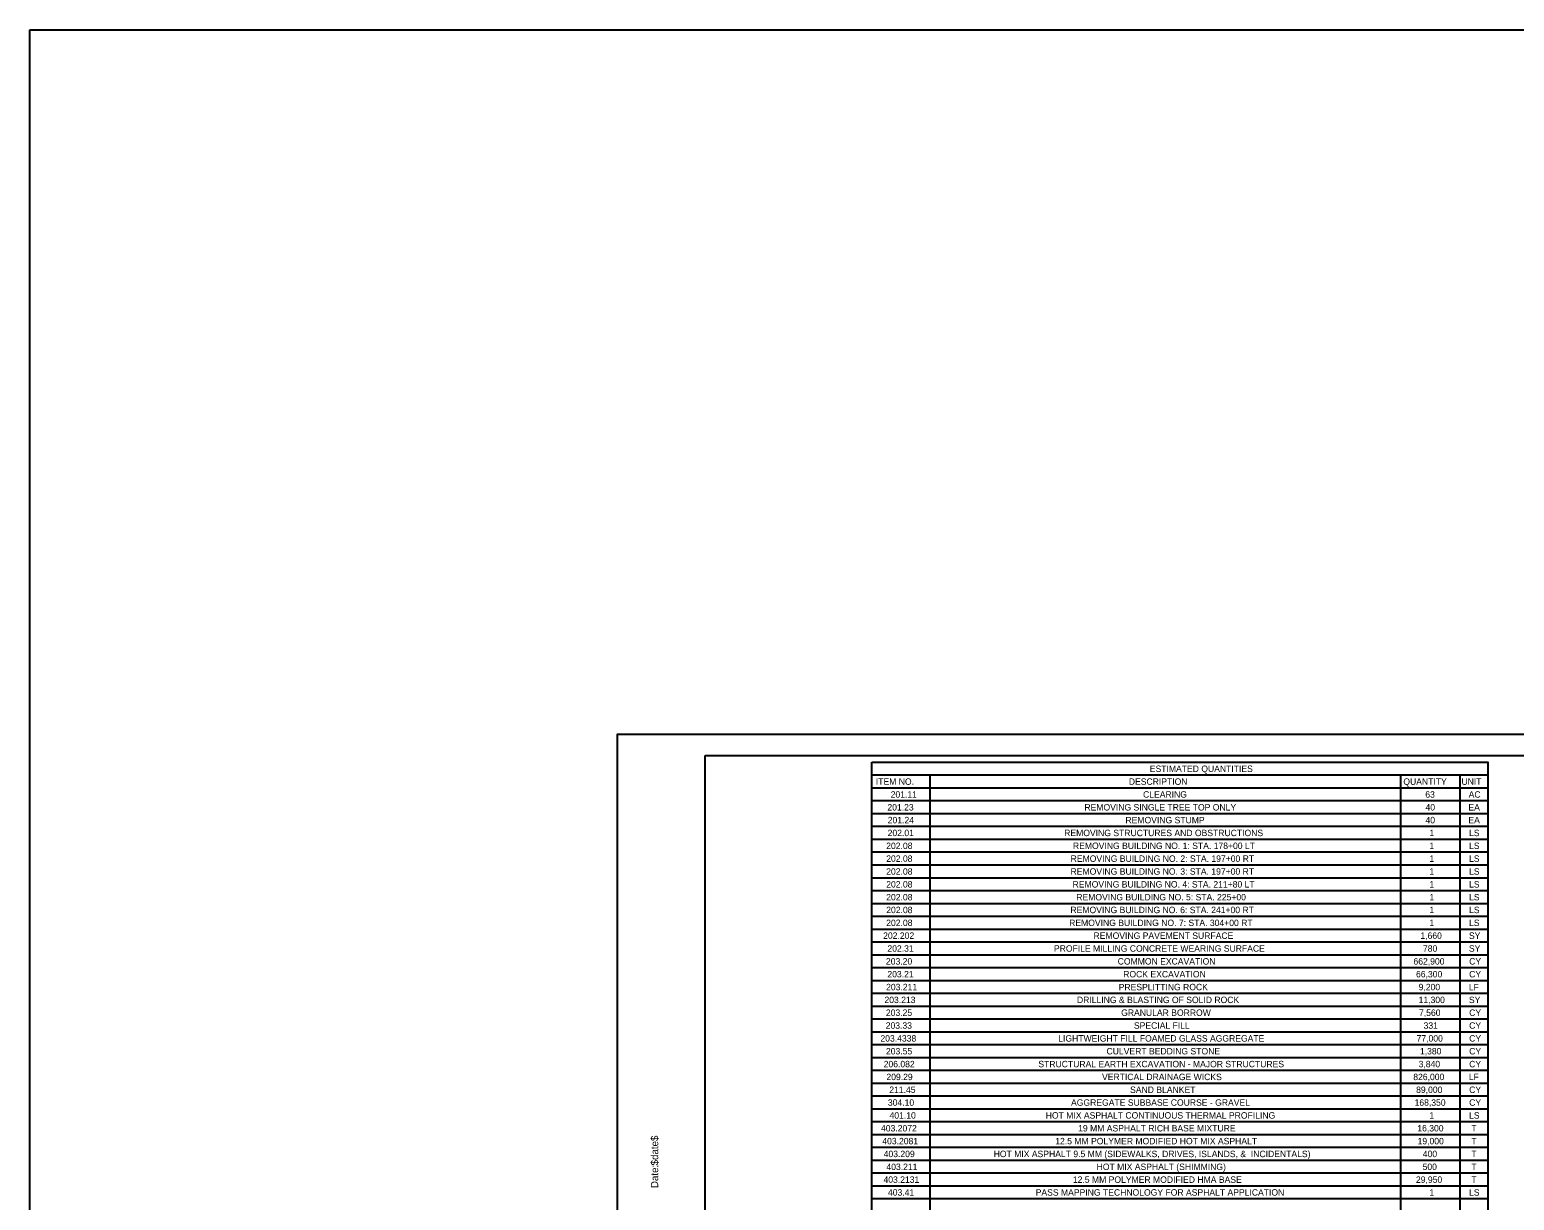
# Model space of a CAD drawing. Extents: x -18.7 to 5.6, y -2.7 to 5.1.
# Drawn here: x -10.815 to -8.539, y 3.303 to 5.098 of the extents above; entities that cross this region are included whole.
import ezdxf

# ---------------------------------------------------------------- set-up
doc = ezdxf.new("R2010")
doc.units = 0
for name, color, linetype in [('ANNOTATION', 7, 'Continuous'), ('BORDER', 7, 'Continuous'), ('Default', 7, 'Continuous'), ('PLOT BOUNDARY', 7, 'Continuous')]:
    doc.layers.add(name, color=color, linetype=linetype)

msp = doc.modelspace()

# ---------------------------------------------------------------- linework, layer by layer
at = {"layer": 'BORDER'}
for p, q in [((-9.524, 3.9551), (-8.5798, 3.9551)), ((-9.4355, 3.9551), (-9.4355, 2.2424)), ((-8.7141, 3.9551), (-8.7141, 2.2424)), ((-8.6227, 3.9551), (-8.6227, 2.2424)), ((-9.524, 3.9354), (-8.5798, 3.9354)), ((-9.524, 3.9157), (-8.5798, 3.9157)), ((-9.524, 3.896), (-8.5798, 3.896)), ((-9.524, 3.8764), (-8.5798, 3.8764)), ((-9.524, 3.8567), (-8.5798, 3.8567)), ((-9.524, 3.837), (-8.5798, 3.837)), ((-9.524, 3.8173), (-8.5798, 3.8173)), ((-9.524, 3.7976), (-8.5798, 3.7976)), ((-9.524, 3.7779), (-8.5798, 3.7779)), ((-9.524, 3.7582), (-8.5798, 3.7582)), ((-9.524, 3.7386), (-8.5798, 3.7386)), ((-9.524, 3.7189), (-8.5798, 3.7189)), ((-9.524, 3.6992), (-8.5798, 3.6992)), ((-9.524, 3.6795), (-8.5798, 3.6795)), ((-9.524, 3.6598), (-8.5798, 3.6598)), ((-9.524, 3.6401), (-8.5798, 3.6401)), ((-9.524, 3.6204), (-8.5798, 3.6204)), ((-9.524, 3.6008), (-8.5798, 3.6008)), ((-9.524, 3.5811), (-8.5798, 3.5811)), ((-9.524, 3.5614), (-8.5798, 3.5614)), ((-9.524, 3.5417), (-8.5798, 3.5417)), ((-9.524, 3.522), (-8.5798, 3.522)), ((-9.524, 3.5023), (-8.5798, 3.5023)), ((-9.524, 3.4826), (-8.5798, 3.4826)), ((-9.524, 3.463), (-8.5798, 3.463)), ((-9.524, 3.4433), (-8.5798, 3.4433)), ((-9.524, 3.4236), (-8.5798, 3.4236)), ((-9.524, 3.4039), (-8.5798, 3.4039)), ((-9.524, 3.3842), (-8.5798, 3.3842)), ((-9.524, 3.3645), (-8.5798, 3.3645)), ((-9.524, 3.3448), (-8.5798, 3.3448)), ((-9.524, 3.3251), (-8.5798, 3.3251)), ((-9.524, 3.3055), (-8.5798, 3.3055))]:
    msp.add_line(p, q, dxfattribs=at)
for points in [[(-9.7797, 3.9848), (-7.1131, 3.9848), (-7.1131, 2.2348), (-9.7797, 2.2348)], [(-9.524, 3.9748), (-8.5798, 3.9748), (-8.5798, 2.2424), (-9.524, 2.2424)]]:
    msp.add_lwpolyline(points, close=True, dxfattribs=at)
at = {"layer": 'Default'}
msp.add_lwpolyline([(-10.8151, 5.0978), (-2.7516, 5.0978), (-2.7516, 1.5028), (-10.8151, 1.5028)], close=True, dxfattribs=at)
at = {"layer": 'PLOT BOUNDARY'}
msp.add_lwpolyline([(-9.9146, 2.1838), (-7.0813, 2.1838), (-7.0813, 4.0171), (-9.9146, 4.0171)], close=True, dxfattribs=at)

# ---------------------------------------------------------------- texts
at = {"layer": 'ANNOTATION'}
for s, height, p in [('201.11', 0.00984, (-9.4954, 3.9203)), ('CLEARING', 0.00984, (-9.1085, 3.9203)), ('63', 0.00984, (-8.6759, 3.9203)), ('AC', 0.00984, (-8.6094, 3.9203)), ('201.23', 0.00984, (-9.5004, 3.9006)), ('REMOVING SINGLE TREE TOP ONLY', 0.009843, (-9.1984, 3.9006)), ('40', 0.00984, (-8.6756, 3.9006)), ('EA', 0.00984, (-8.6098, 3.9006)), ('202.01', 0.00984, (-9.5, 3.8613)), ('201.24', 0.00984, (-9.4999, 3.881)), ('REMOVING STRUCTURES AND OBSTRUCTIONS', 0.009843, (-9.2294, 3.8613)), ('REMOVING STUMP', 0.009843, (-9.1355, 3.881)), ('40', 0.00984, (-8.6756, 3.881)), ('1', 0.00984, (-8.6695, 3.8613)), ('EA', 0.00984, (-8.6098, 3.881)), ('LS', 0.00984, (-8.6088, 3.8613)), ('202.08', 0.00984, (-9.5022, 3.8416)), ('REMOVING BUILDING NO. 1: STA. 178+00 LT', 0.009843, (-9.216, 3.8416)), ('1', 0.00984, (-8.6695, 3.8416)), ('LS', 0.00984, (-8.6088, 3.8416)), ('202.08', 0.00984, (-9.5022, 3.8219)), ('REMOVING BUILDING NO. 2: STA. 197+00 RT', 0.009843, (-9.2195, 3.8219)), ('1', 0.00984, (-8.6695, 3.8219)), ('LS', 0.00984, (-8.6088, 3.8219)), ('202.08', 0.00984, (-9.5022, 3.8022)), ('REMOVING BUILDING NO. 3: STA. 197+00 RT', 0.009843, (-9.2196, 3.8022)), ('1', 0.00984, (-8.6695, 3.8022)), ('LS', 0.00984, (-8.6088, 3.8022)), ('202.08', 0.00984, (-9.5022, 3.7825)), ('REMOVING BUILDING NO. 4: STA. 211+80 LT', 0.009843, (-9.2165, 3.7825)), ('1', 0.00984, (-8.6695, 3.7825)), ('LS', 0.00984, (-8.6088, 3.7825)), ('202.08', 0.00984, (-9.5022, 3.7628)), (' REMOVING BUILDING NO. 5: STA. 225+00', 0.009843, (-9.2145, 3.7628)), ('1', 0.00984, (-8.6695, 3.7628)), ('LS', 0.00984, (-8.6088, 3.7628)), ('202.08', 0.00984, (-9.5022, 3.7432)), ('202.08', 0.00984, (-9.5022, 3.7235)), ('REMOVING BUILDING NO. 7: STA. 304+00 RT', 0.009843, (-9.2218, 3.7235)), ('REMOVING BUILDING NO. 6: STA. 241+00 RT', 0.009843, (-9.2198, 3.7432)), ('1', 0.00984, (-8.6695, 3.7432)), ('1', 0.00984, (-8.6695, 3.7235)), ('LS', 0.00984, (-8.6088, 3.7432)), ('LS', 0.00984, (-8.6088, 3.7235)), ('202.202', 0.00984, (-9.5069, 3.7038)), ('REMOVING PAVEMENT SURFACE', 0.009843, (-9.1844, 3.7038)), ('1,660', 0.00984, (-8.6834, 3.7038)), ('SY', 0.00984, (-8.609, 3.7038)), ('202.31', 0.00984, (-9.5004, 3.6841)), ('PROFILE MILLING CONCRETE WEARING SURFACE', 0.009843, (-9.2451, 3.6841)), ('780', 0.00984, (-8.6795, 3.6841)), ('SY', 0.00984, (-8.609, 3.6841)), ('203.20', 0.00984, (-9.5026, 3.6644)), ('COMMON EXCAVATION', 0.009843, (-9.1474, 3.6644)), ('662,900', 0.00984, (-8.694, 3.6644)), ('CY', 0.00984, (-8.6086, 3.6644)), ('203.21', 0.00984, (-9.5004, 3.6447)), ('ROCK EXCAVATION', 0.009843, (-9.1389, 3.6447)), ('66,300', 0.00984, (-8.6901, 3.6447)), ('CY', 0.00984, (-8.6086, 3.6447)), ('203.211', 0.00984, (-9.5024, 3.625)), ('PRESPLITTING ROCK', 0.009843, (-9.1459, 3.625)), ('9,200', 0.00984, (-8.6861, 3.625)), ('LF', 0.00984, (-8.6092, 3.625)), ('203.213', 0.00984, (-9.5049, 3.6053)), ('203.25', 0.00984, (-9.5027, 3.5857)), ('DRILLING & BLASTING OF SOLID ROCK       ', 0.009843, (-9.2098, 3.6053)), ('GRANULAR BORROW', 0.009843, (-9.1421, 3.5857)), ('11,300', 0.00984, (-8.6861, 3.6053)), ('7,560', 0.00984, (-8.6855, 3.5857)), ('SY', 0.00984, (-8.609, 3.6053)), ('CY', 0.00984, (-8.6086, 3.5857)), ('203.33', 0.00984, (-9.503, 3.566)), ('SPECIAL FILL', 0.009843, (-9.1225, 3.566)), ('331', 0.00984, (-8.6785, 3.566)), ('CY', 0.00984, (-8.6086, 3.566)), ('203.4338', 0.00984, (-9.5111, 3.5463)), ('LIGHTWEIGHT FILL FOAMED GLASS AGGREGATE', 0.009843, (-9.2385, 3.5463)), ('77,000', 0.00984, (-8.6892, 3.5463)), ('CY', 0.00984, (-8.6086, 3.5463)), ('203.55', 0.00984, (-9.5026, 3.5266)), ('CULVERT BEDDING STONE', 0.009843, (-9.1645, 3.5266)), ('1,380', 0.00984, (-8.6841, 3.5266)), ('CY', 0.00984, (-8.6086, 3.5266)), ('206.082', 0.00984, (-9.5061, 3.5069)), ('STRUCTURAL EARTH EXCAVATION - MAJOR STRUCTURES', 0.009843, (-9.269, 3.5069)), ('3,840', 0.00984, (-8.6861, 3.5069)), ('CY', 0.00984, (-8.6086, 3.5069)), ('209.29', 0.00984, (-9.5019, 3.4872)), ('VERTICAL DRAINAGE WICKS', 0.009843, (-9.1714, 3.4872)), ('826,000', 0.00984, (-8.6943, 3.4872)), ('LF', 0.00984, (-8.6092, 3.4872)), ('211.45', 0.00984, (-9.4975, 3.4675)), ('SAND BLANKET', 0.009843, (-9.1284, 3.4675)), ('89,000', 0.00984, (-8.6899, 3.4675)), ('CY', 0.00984, (-8.6086, 3.4675)), ('304.10', 0.00984, (-9.4996, 3.4479)), ('401.10', 0.00984, (-9.4971, 3.4282)), ('HOT MIX ASPHALT CONTINUOUS THERMAL PROFILING', 0.009843, (-9.2577, 3.4282)), ('AGGREGATE SUBBASE COURSE - GRAVEL', 0.009843, (-9.2189, 3.4479)), ('168,350', 0.00984, (-8.6923, 3.4479)), ('1', 0.00984, (-8.6695, 3.4282)), ('CY', 0.00984, (-8.6086, 3.4479)), ('LS', 0.00984, (-8.6088, 3.4282)), ('403.2072', 0.00984, (-9.5102, 3.4085)), ('19 MM ASPHALT RICH BASE MIXTURE', 0.009843, (-9.208, 3.4085)), ('16,300', 0.00984, (-8.6881, 3.4085)), ('T', 0.00984, (-8.6053, 3.4085)), ('403.2081', 0.00984, (-9.5082, 3.3888)), ('12.5 MM POLYMER MODIFIED HOT MIX ASPHALT', 0.009843, (-9.2431, 3.3888)), ('19,000', 0.00984, (-8.6877, 3.3888)), ('T', 0.00984, (-8.6053, 3.3888)), ('403.209', 0.00984, (-9.5061, 3.3691)), ('HOT MIX ASPHALT 9.5 MM (SIDEWALKS, DRIVES, ISLANDS, &  INCIDENTALS)', 0.009843, (-9.3375, 3.3691)), ('400', 0.00984, (-8.6797, 3.3691)), ('T', 0.00984, (-8.6053, 3.3691)), ('403.211', 0.00984, (-9.5019, 3.3494)), ('HOT MIX ASPHALT (SHIMMING)', 0.009843, (-9.1797, 3.3494)), ('500', 0.00984, (-8.68, 3.3494)), ('T', 0.00984, (-8.6053, 3.3494)), ('403.2131', 0.00984, (-9.5064, 3.3297)), ('12.5 MM POLYMER MODIFIED HMA BASE', 0.009843, (-9.2161, 3.3297)), ('29,950', 0.00984, (-8.6902, 3.3297)), ('T', 0.00984, (-8.6053, 3.3297)), ('403.41', 0.00984, (-9.4995, 3.3101)), ('PASS MAPPING TECHNOLOGY FOR ASPHALT APPLICATION', 0.009843, (-9.2731, 3.3101)), ('1', 0.00984, (-8.6695, 3.3101)), ('LS', 0.00984, (-8.6088, 3.3101))]:
    msp.add_text(s, height=height, dxfattribs=at).set_placement(p)
at = {"layer": 'BORDER'}
for s, height, p in [('ESTIMATED QUANTITIES', 0.009843, (-9.0982, 3.9597)), ('ITEM NO.', 0.00984, (-9.5181, 3.94)), ('DESCRIPTION', 0.009843, (-9.1303, 3.94)), ('QUANTITY', 0.00984, (-8.7095, 3.94)), ('UNIT', 0.00984, (-8.6204, 3.94))]:
    msp.add_text(s, height=height, dxfattribs=at).set_placement(p)
for s, p in [('$date$', (-9.8517, 3.3565)), ('Date:', (-9.8517, 3.3217))]:
    msp.add_text(s, height=0.01116, rotation=90, dxfattribs=at).set_placement(p)

doc.saveas('drawing.dxf')
